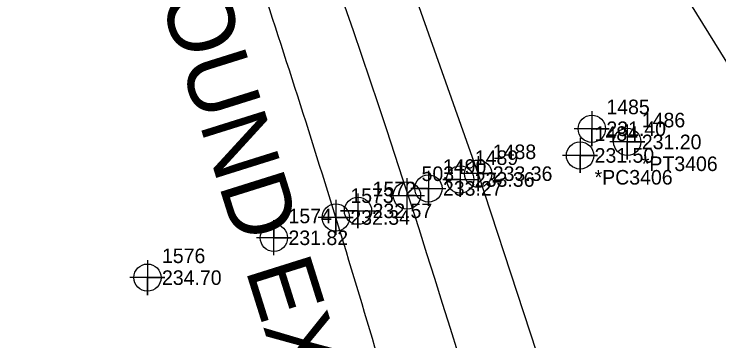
# Model space of a CAD drawing. Extents: x 2130621 to 2131998, y 642516 to 644503.
# Drawn here: x 2131082.7 to 2131203.6, y 643834.2 to 643890.3 of the extents above; entities that cross this region are included whole.
import ezdxf

# ---------------------------------------------------------------- set-up
doc = ezdxf.new("R2010")
doc.units = 0
for name, color, linetype in [('Cogo Default Point CELL', 7, 'Continuous'), ('COGO Default Point Number', 7, 'Continuous'), ('Exist Other Culture Area Outline Cogo Comment', 7, 'Continuous'), ('Exist Other Culture Area Outline Cogo Elevation', 7, 'Continuous'), ('Exist Other Culture Area Outline Cogo Number', 7, 'Continuous'), ('Exist Other Culture Area Outline Cogo Point CELL', 7, 'Continuous'), ('Exist Roads EOP', 7, 'Continuous'), ('Exist Roads EOP Cogo Elevation', 7, 'Continuous'), ('Exist Roads EOP Cogo Number', 7, 'Continuous'), ('Exist Roads EOP Cogo Point CELL', 7, 'Continuous'), ('Exist Roads EOT Cogo Elevation', 7, 'Continuous'), ('Exist Roads EOT Cogo Number', 7, 'Continuous'), ('Exist Roads EOT Cogo Point CELL', 7, 'Continuous'), ('Exist Roads EOT Text', 7, 'Continuous'), ('Exist Roads Soil Cogo Elevation', 7, 'Continuous'), ('Exist Roads Soil Cogo Number', 7, 'Continuous'), ('Exist Roads Soil Cogo Point CELL', 7, 'Continuous'), ('Exist Vegetation Woods Line Cogo Elevation', 7, 'Continuous'), ('Exist Vegetation Woods Line Cogo Number', 7, 'Continuous'), ('Exist Vegetation Woods Line Cogo Point CELL', 7, 'Continuous'), ('Prop Horizontal Alignment', 7, 'Continuous')]:
    doc.layers.add(name, color=color, linetype=linetype)

msp = doc.modelspace()

# ---------------------------------------------------------------- linework, layer by layer
at = {"layer": 'Cogo Default Point CELL'}
for points in [[(2131150.07, 643862.17), (2131150.07, 643859.17)], [(2131147.07, 643859.17), (2131150.07, 643859.17)], [(2131150.07, 643859.17), (2131153.07, 643859.17)], [(2131150.07, 643859.17), (2131150.07, 643856.17)]]:
    msp.add_lwpolyline(points, dxfattribs=at)
msp.add_circle((2131150.07, 643859.17), 2.34, dxfattribs=at)
at = {"layer": 'Exist Other Culture Area Outline Cogo Point CELL'}
for points in [[(2131181.77, 643873.64), (2131181.77, 643867.64), (2131181.77, 643870.64), (2131184.77, 643870.64), (2131178.77, 643870.64)], [(2131187.85, 643871.38), (2131187.85, 643865.38), (2131187.85, 643868.38), (2131190.85, 643868.38), (2131184.85, 643868.38)], [(2131179.75, 643869.06), (2131179.75, 643863.06), (2131179.75, 643866.06), (2131182.75, 643866.06), (2131176.75, 643866.06)]]:
    msp.add_lwpolyline(points, dxfattribs=at)
for centre in [(2131181.77, 643870.64), (2131187.85, 643868.38), (2131179.75, 643866.06)]:
    msp.add_circle(centre, 2.34, dxfattribs=at)
at = {"layer": 'Exist Roads EOP'}
for points in [[(2131125, 644001.4), (2131151.48, 643966.59), (2131158.59, 643957.1), (2131179.44, 643923.18), (2131206.93, 643878.75), (2131233.55, 643835.75)], [(2131264.27, 643222.56), (2131259.88, 643269.33), (2131257.02, 643319.4), (2131254.26, 643369.65), (2131250.08, 643419.42), (2131246.15, 643469.03), (2131240.84, 643519.13), (2131234.37, 643568.56), (2131226.33, 643620.18), (2131217.03, 643668.71), (2131205.62, 643717.61), (2131192.06, 643767.26), (2131177.97, 643815.09), (2131162.29, 643862.93), (2131145.36, 643910.85), (2131126.91, 643957.29), (2131112.37, 643996.12)]]:
    msp.add_lwpolyline(points, dxfattribs=at)
msp.add_spline([(2131166.25, 643216.7), (2131171.81, 643218.72), (2131182.37, 643223.97), (2131191.81, 643231.15), (2131200.5, 643239.7), (2131208.81, 643249.07), (2131216.07, 643259), (2131218.72, 643264.35), (2131220.54, 643270.1), (2131222.84, 643282.01), (2131224.36, 643293.92), (2131224.88, 643317.79), (2131222.06, 643367.67), (2131218.54, 643416.81), (2131214.32, 643466.35), (2131209.17, 643515.67), (2131202.79, 643565.15), (2131195.05, 643613.99), (2131186.4, 643662.48), (2131176.01, 643711.41), (2131164.62, 643759.89), (2131151.87, 643807.85), (2131137.86, 643855.41), (2131122.57, 643902.86), (2131105.96, 643949.49), (2131091.53, 643988.04)], degree=3, dxfattribs=at)
at = {"layer": 'Exist Roads EOP Cogo Point CELL'}
for points in [[(2131162.29, 643865.93), (2131162.29, 643859.93), (2131162.29, 643862.93), (2131165.29, 643862.93), (2131159.29, 643862.93)], [(2131137.86, 643858.41), (2131137.86, 643852.41), (2131137.86, 643855.41), (2131140.86, 643855.41), (2131134.86, 643855.41)]]:
    msp.add_lwpolyline(points, dxfattribs=at)
for centre in [(2131162.29, 643862.93), (2131137.86, 643855.41)]:
    msp.add_circle(centre, 2.34, dxfattribs=at)
at = {"layer": 'Exist Roads EOT Cogo Point CELL'}
for points in [[(2131159.21, 643864.93), (2131159.21, 643858.93), (2131159.21, 643861.93), (2131156.21, 643861.93), (2131162.21, 643861.93)], [(2131153.74, 643863.4), (2131153.74, 643857.4), (2131153.74, 643860.4), (2131150.74, 643860.4), (2131156.74, 643860.4)], [(2131141.67, 643859.55), (2131141.67, 643853.55), (2131141.67, 643856.55), (2131138.67, 643856.55), (2131144.67, 643856.55)]]:
    msp.add_lwpolyline(points, dxfattribs=at)
for centre in [(2131159.21, 643861.93), (2131153.74, 643860.4), (2131141.67, 643856.55)]:
    msp.add_circle(centre, 2.34, dxfattribs=at)
at = {"layer": 'Exist Roads Soil Cogo Point CELL'}
msp.add_lwpolyline([(2131127.25, 643848.92), (2131127.25, 643854.92), (2131127.25, 643851.92), (2131130.25, 643851.92), (2131124.25, 643851.92)], dxfattribs=at)
msp.add_circle((2131127.25, 643851.92), 2.34, dxfattribs=at)
at = {"layer": 'Exist Vegetation Woods Line Cogo Point CELL'}
msp.add_lwpolyline([(2131105.55, 643848.08), (2131105.55, 643842.08), (2131105.55, 643845.08), (2131108.55, 643845.08), (2131102.55, 643845.08)], dxfattribs=at)
msp.add_circle((2131105.55, 643845.08), 2.34, dxfattribs=at)
at = {"layer": 'Prop Horizontal Alignment'}
msp.add_arc((2129448.47, 643307.66), 1788.96, 4.14306, 22.49968, dxfattribs=at)

# ---------------------------------------------------------------- texts
at = {"layer": 'COGO Default Point Number'}
msp.add_text('503', height=2.5, dxfattribs=at).set_placement((2131152.57, 643861.67))
at = {"layer": 'Exist Other Culture Area Outline Cogo Comment'}
for s, p in [('*PT3406', (2131190.35, 643863.38)), ('*PC3406', (2131182.25, 643861.06))]:
    msp.add_text(s, height=2.5, dxfattribs=at).set_placement(p)
at = {"layer": 'Exist Other Culture Area Outline Cogo Elevation'}
for s, p in [('231.40', (2131184.27, 643869.39)), ('231.20', (2131190.35, 643867.13)), ('231.50', (2131182.25, 643864.81))]:
    msp.add_text(s, height=2.5, dxfattribs=at).set_placement(p)
at = {"layer": 'Exist Other Culture Area Outline Cogo Number'}
for s, p in [('1485', (2131184.27, 643873.14)), ('1486', (2131190.35, 643870.88)), ('1484', (2131182.25, 643868.56))]:
    msp.add_text(s, height=2.5, dxfattribs=at).set_placement(p)
at = {"layer": 'Exist Roads EOP Cogo Elevation'}
for s, p in [('233.36', (2131164.79, 643861.68)), ('232.34', (2131140.36, 643854.16))]:
    msp.add_text(s, height=2.5, dxfattribs=at).set_placement(p)
at = {"layer": 'Exist Roads EOP Cogo Number'}
for s, p in [('1488', (2131164.79, 643865.43)), ('1573', (2131140.36, 643857.91))]:
    msp.add_text(s, height=2.5, dxfattribs=at).set_placement(p)
at = {"layer": 'Exist Roads EOT Cogo Elevation'}
for s, p in [('233.36', (2131161.71, 643860.68)), ('233.27', (2131156.24, 643859.15)), ('232.57', (2131144.17, 643855.3))]:
    msp.add_text(s, height=2.5, dxfattribs=at).set_placement(p)
at = {"layer": 'Exist Roads EOT Cogo Number'}
for s, p in [('1489', (2131161.71, 643864.43)), ('1490', (2131156.24, 643862.9)), ('1572', (2131144.17, 643859.05))]:
    msp.add_text(s, height=2.5, dxfattribs=at).set_placement(p)
at = {"layer": 'Exist Roads EOT Text'}
for s, rotation, p in [('I-40 EAST BOUND LANE', 303.2392, (2131132.75, 644019.45)), ('I-40 EAST BOUND EXIT RAMP', 287.4395, (2131082.27, 643973.9))]:
    msp.add_text(s, height=11.3735, rotation=rotation, dxfattribs=at).set_placement(p)
at = {"layer": 'Exist Roads Soil Cogo Elevation'}
msp.add_text('231.82', height=2.5, dxfattribs=at).set_placement((2131129.75, 643850.67))
at = {"layer": 'Exist Roads Soil Cogo Number'}
msp.add_text('1574', height=2.5, dxfattribs=at).set_placement((2131129.75, 643854.42))
at = {"layer": 'Exist Vegetation Woods Line Cogo Elevation'}
msp.add_text('234.70', height=2.5, dxfattribs=at).set_placement((2131108.05, 643843.83))
at = {"layer": 'Exist Vegetation Woods Line Cogo Number'}
msp.add_text('1576', height=2.5, dxfattribs=at).set_placement((2131108.05, 643847.58))

doc.saveas('drawing.dxf')
